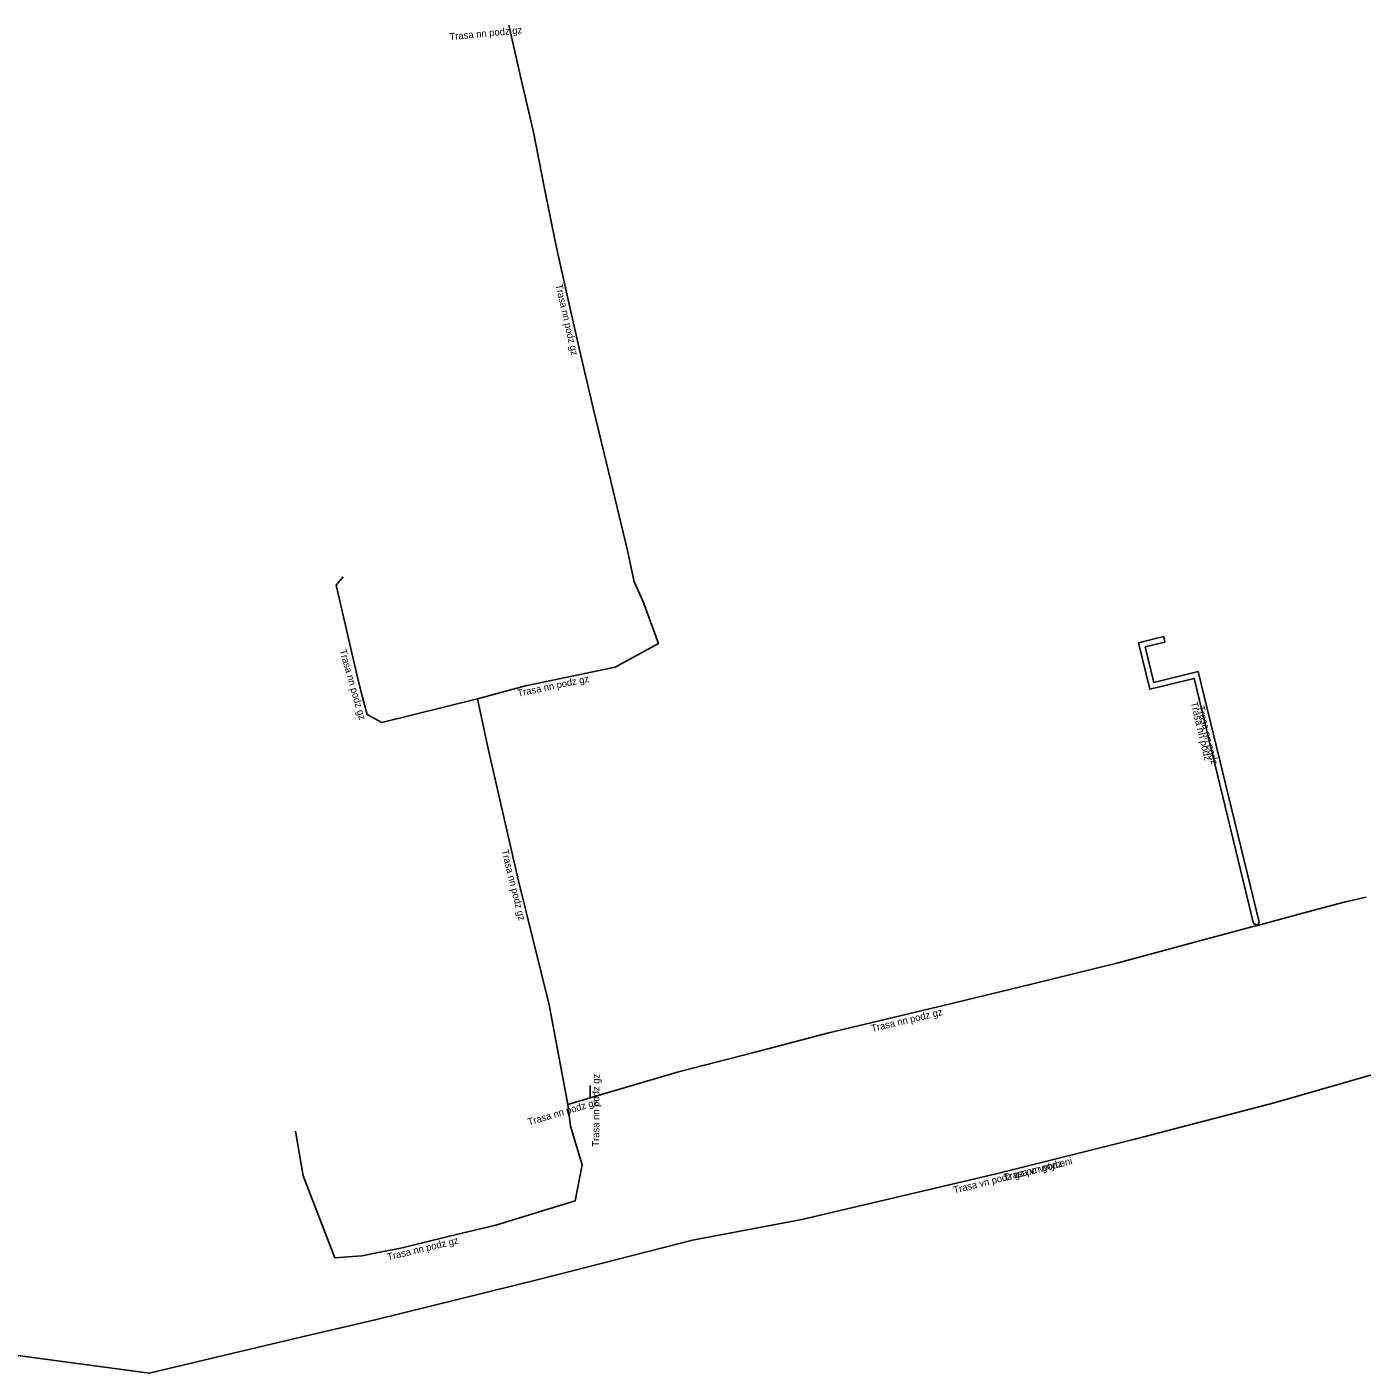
# Model space of a CAD drawing. Extents: x -473162 to -472638, y -1107075 to -1106812.
# Drawn here: x -472870 to -472775.4, y -1107033.1 to -1106937.8 of the extents above; entities that cross this region are included whole.
import ezdxf

# ---------------------------------------------------------------- set-up
doc = ezdxf.new("R2010")
doc.units = 0
for name, color, linetype in [('Popiskový text - Ostatní atributy Trasy', 7, 'Continuous'), ('Spojnice NN', 7, 'Continuous'), ('Spojnice VN', 7, 'Continuous')]:
    doc.layers.add(name, color=color, linetype=linetype)

msp = doc.modelspace()

# ---------------------------------------------------------------- linework, layer by layer
at = {"layer": 'Spojnice NN'}
for points in [[(-472825.245, -1106981.435), (-472826.36, -1106978.41), (-472826.97, -1106977.07), (-472827.45, -1106974.84), (-472828.94, -1106968.67), (-472829.845, -1106964.85), (-472830.75, -1106961.03), (-472831.64, -1106957.102), (-472832.53, -1106953.175), (-472833.315, -1106949.195), (-472834.1, -1106945.215), (-472834.958, -1106941.575), (-472835.852, -1106937.645)], [(-472838.076, -1106985.367), (-472844.845, -1106987.045), (-472845.88, -1106986.48), (-472846.23, -1106985.25), (-472846.55, -1106983.94), (-472848.08, -1106977.295), (-472847.59, -1106976.71)], [(-472789.413, -1106981.157), (-472789.463, -1106980.952), (-472791.249, -1106981.386), (-472790.451, -1106984.674), (-472787.303, -1106983.91), (-472783.095, -1107001.278), (-472782.822, -1107001.411)], [(-472789.413, -1106981.157), (-472789.369, -1106981.341), (-472790.766, -1106981.68), (-472790.157, -1106984.191), (-472787.008, -1106983.427), (-472782.708, -1107001.173), (-472782.822, -1107001.411)], [(-472838.076, -1106985.367), (-472834.66, -1106984.435), (-472831.492, -1106983.772), (-472828.325, -1106983.11), (-472825.245, -1106981.435)], [(-472831.683, -1107014.101), (-472833.005, -1107007.04), (-472834.112, -1107002.552), (-472835.22, -1106998.065), (-472836.258, -1106993.525), (-472837.295, -1106988.985), (-472838.076, -1106985.367)], [(-472775.108, -1106999.412), (-472776.67, -1106999.755), (-472779.948, -1107000.638), (-472782.822, -1107001.411)], [(-472782.822, -1107001.411), (-472783.225, -1107001.52), (-472787.952, -1107002.795), (-472792.68, -1107004.07), (-472798.825, -1107005.565), (-472804.97, -1107007.06), (-472813.175, -1107009.025), (-472818.502, -1107010.402), (-472823.83, -1107011.78), (-472830.087, -1107013.629)], [(-472830.087, -1107013.629), (-472830.082, -1107012.753)], [(-472830.087, -1107013.629), (-472831.683, -1107014.101)], [(-472850.955, -1107015.975), (-472850.43, -1107019.15), (-472848.17, -1107024.955), (-472846.265, -1107024.82), (-472844.882, -1107024.542), (-472843.5, -1107024.265), (-472840.14, -1107023.45), (-472836.78, -1107022.635), (-472831.165, -1107020.925), (-472830.65, -1107018.365), (-472831.475, -1107015.635), (-472831.683, -1107014.101)]]:
    msp.add_lwpolyline(points, dxfattribs=at)
at = {"layer": 'Spojnice VN'}
msp.add_lwpolyline([(-472875.93, -1107028.105), (-472871, -1107031.825), (-472861.334, -1107033.124), (-472850.8, -1107030.635), (-472845.315, -1107029.36), (-472833.57, -1107026.445), (-472822.845, -1107023.715), (-472815.105, -1107022.245), (-472801.34, -1107019), (-472791.505, -1107016.55), (-472781.55, -1107013.95), (-472772.185, -1107011.27), (-472769.485, -1107010.31), (-472760.405, -1107005.475), (-472750.82, -1106999.465), (-472737.825, -1106992.205), (-472734.315, -1106989.81), (-472728.85, -1106987.34), (-472726.784, -1106986.168), (-472724.295, -1106985.16)], dxfattribs=at)
msp.add_lwpolyline([(-472875.93, -1107028.105), (-472871, -1107031.825), (-472861.334, -1107033.124), (-472850.8, -1107030.635), (-472845.315, -1107029.36), (-472833.57, -1107026.445), (-472822.845, -1107023.715), (-472815.105, -1107022.245), (-472801.34, -1107019), (-472791.505, -1107016.55), (-472781.55, -1107013.95), (-472772.185, -1107011.27), (-472769.485, -1107010.31), (-472760.405, -1107005.475), (-472750.82, -1106999.465), (-472737.825, -1106992.205), (-472734.315, -1106989.81), (-472728.85, -1106987.34), (-472726.784, -1106986.168), (-472724.295, -1106985.16)], dxfattribs=at)

# ---------------------------------------------------------------- texts
at = {"layer": 'Popiskový text - Ostatní atributy Trasy'}
for s, rotation, p in [('Trasa nn podz gz', 5.49232, (-472840.03, -1106938.7)), ('Trasa nn podz gz', 282.76643, (-472832.549, -1106956.03)), ('Trasa nn podz gz', 285.88385, (-472847.852, -1106981.924)), ('Trasa nn podz gz', 11.82028, (-472835.188, -1106985.209)), ('Trasa nn podz', 283.61944, (-472787.557, -1106985.622)), ('Trasa nn podz', 283.62071, (-472787.077, -1106985.902)), ('Trasa nn podz gz', 283.87088, (-472836.375, -1106996.097)), ('Trasa nn podz gz', 13.468, (-472810.116, -1107008.961)), ('Trasa nn podz gz', 89.65692, (-472829.457, -1107017.088)), ('Trasa nn podz gz', 16.46677, (-472834.435, -1107015.592)), ('Trasa vn podz gz po vytyceni', 13.98826, (-472804.295, -1107020.406)), ('Trasa vn podz', 13.98826, (-472800.719, -1107019.515)), ('Trasa nn podz gz', 13.63432, (-472844.401, -1107025.153))]:
    msp.add_text(s, height=0.5, rotation=rotation, dxfattribs=at).set_placement(p)

doc.saveas('drawing.dxf')
